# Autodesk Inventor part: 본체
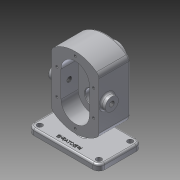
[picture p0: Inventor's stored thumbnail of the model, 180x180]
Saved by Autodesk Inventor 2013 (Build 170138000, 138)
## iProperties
Created: 2019-03
Part Number: 본체
Material: 알루미늄 6061
Document SubType Name: Modeling
Designer: Administrator
Density: 2.71 g/cm^3
Mass: 1193.14 g
Surface Area: 720.724 cm^2
Volume: 440.275 cm^3
Author: Administrator
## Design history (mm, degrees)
sketch "스케치2"
  geometry: L1 (-40, 60)-(40, 60); L2 (40, 60)-(40, -60); L3 (40, -60)-(-40, -60); L4 (-40, -60)-(-40, 60); A1 r 60 centre (0, 0) between (-40, -44.721) and (40, -44.721); A2 r 60 centre (0, 0) between (40, 44.721) and (-40, 44.721); 3 further points
  constraints: 8 end point, 5 point on circle, 4 point on line, 2 centre point, 2 midpoint, 2 parallel, 1 coincident, 1 horizontal, 1 horizontal alignment, 1 perpendicular, 1 vertical alignment
  dimensions: "d0" = 80 distance between parallel lines of L2 L4; "d2" = 120 distance of L3.end L1.start; "d5" = 60 radius of A2; "d6" = 60 radius of A1
extrude "돌출1" new body sketch "스케치2" distance "d7" = 53; taper "d8" = 0 deg
sketch "스케치3"
  geometry: L1 (-40, 44.721)-(-40, -44.721) reference; L2 (-24, 22)-(-24, -22); L3 (24, -22)-(24, 22); A1 r 60 centre (0, 0) between (40, 44.721) and (-40, 44.721) reference; A2 r 24 centre (0, 22) between (24, 22) and (-24, 22); A3 r 24 centre (0, -22) between (-24, -22) and (24, -22)
  constraints: 4 end point, 4 point on circle, 2 centre point, 2 parallel, 2 tangent, 2 vertical alignment
  dimensions: "d9" = 24 radius of A2; "d10" = 24 radius of A3; "d11" = 44 distance of A3.centre A2.centre; "d12" = 22 distance of A1.centre A2.centre
extrude "돌출2" cut sketch "스케치3" distance "d13" = 29; taper "d14" = 0 deg
sketch "스케치4"
  geometry: C1 r 12.5 at (0, 22); C2 r 12.5 at (0, -22); A1 r 24 centre (0, -22) between (-24, -22) and (24, -22) reference; A2 r 24 centre (0, 22) between (24, 22) and (-24, 22) reference; 1 further point
  constraints: 2 centre point, 2 coincident
  dimensions: "d15" = 12.5 radius of C1; "d16" = 12.5 radius of C2
extrude "돌출3" cut sketch "스케치4" distance "d17" = 15; taper "d18" = 0 deg
sketch "스케치5"
  geometry: C1 r 12.5 at (0, 0) reference; C2 r 8.5 at (0, 0); 1 further point
  constraints: 1 centre point, 1 coincident
  dimensions: "d19" = 8.5 radius of C2
extrude "돌출4" cut sketch "스케치5" stored distance "d20" = 15; taper "d21" = 0 deg
sketch "스케치6"
  geometry: C1 r 8.5 at (0, 22) reference; C2 r 19 at (0, 22)
  constraints: 1 centre point, 1 coincident
  dimensions: "d22" = 19 radius of C2
extrude "돌출5" join sketch "스케치6" distance "d23" = 17; taper "d24" = 0 deg
sketch "스케치7"
  geometry: L1 (3, -17)-(41, -17) reference; L2 (30.5, 9)-(30.5, -17) reference; L3 (13.5, 9)-(13.5, -17) reference; L4 (22, 8.572)-(22, -17); L5 (22, -9.7)-(35.5, -9.7); L6 (36, -10.2)-(36, -16.3); L7 (36, -16.3)-(22, -16.3); L8 (22, -16.3)-(22, -9.7); L9 (36, -16.3)-(36.404, -17); L10 (36, -16.3)-(39.088, -16.3); L11 (36, -16.3)-(36, -19.794); A1 r 0.5 centre (35.5, -10.2) between (36, -10.2) and (35.5, -9.7); 2 further points
  constraints: 16 end point, 4 point on line, 3 parallel, 2 horizontal, 2 perpendicular, 2 point on circle, 2 tangent, 1 centre point, 1 midpoint
  dimensions: "d25" = 6.6 distance of point (36, -9.7) L6.end; "d28" = 7.3 distance from line of L4.end L5; "d30" = 28 diameter of L6 L4; "d31" = 30 deg angle of L11 L9; "d32" = 0.5 radius of A1
revolve "회전1" sketch "스케치7" stored, may be unused: angle "d33" = 90 deg
sketch "스케치8"
  geometry: C1 r 12.5 at (0, 22) reference; A1 r 24 centre (0, -22) between (-24, -22) and (24, -22) reference; A2 r 24 centre (0, 22) between (24, 22) and (-24, 22) reference; A3 r 31 centre (0, 22) between (0, 53) and (-31, 22); A4 r 31 centre (0, -22) between (31, -22) and (0, -53); 2 further points
  constraints: 6 point on circle, 4 vertical alignment, 2 centre point, 2 coincident, 2 horizontal alignment
  dimensions: "d34" = 31 radius of A3; "d35" = 31 radius of A4
hole "구멍1" sketch "스케치8" at (0, 53), (-31, 22), (31, 22), (31, -22), (0, -53), (-31, -22) diameter "d36" = 4.134; stored, may be unused: countersink angle "d40" = 90 deg, drill point angle "d42" = 118 deg; dims "d37" = 10, "d38" = 4, "d39" = 2, "d41" = 12
sketch "스케치9"
  geometry: L1 (0, 0)-(0, 89.443) reference; L2 (-53, 0)-(-53, 89.443) reference; C1 r 11 at (-39, 44.721); 2 further points
  constraints: 1 centre point, 1 horizontal alignment, 1 midpoint
  dimensions: "d43" = 22 diameter of C1; "d45" = 14 distance from line of L2 C1.centre
extrude "돌출6" join sketch "스케치9" distance "d46" = 8; taper "d47" = 0 deg
sketch "스케치10"
  geometry: C1 r 11 at (0, 0) reference; 1 further point
sketch "스케치11"
  geometry: C1 r 11 at (0, 0) reference; 1 further point
hole "구멍2" sketch "스케치11" at (0, 0) diameter "d48" = 8.376; stored, may be unused: countersink angle "d52" = 90 deg, drill point angle "d54" = 118 deg; dims "d49" = 30, "d50" = 4, "d51" = 2, "d53" = 12
hole "구멍3" sketch "스케치10" diameter "d55" = 8.376; stored, may be unused: countersink angle "d59" = 90 deg, drill point angle "d61" = 118 deg; dims "d56" = 100, "d57" = 4, "d58" = 2, "d60" = 12
node "작업 평면2"
sketch "스케치12"
  geometry: L1 (40, 53)-(-40, 53) reference; L2 (40, 0)-(-40, 0) reference; L3 (-40, 50)-(-48, 50) reference; L4 (-40, 28)-(-48, 28) reference; L5 (-40, 28)-(-48, 28) reference; L6 (-40, 28)-(-48, 28) reference; L7 (-44, 28)-(-44, 50); L8 (-60, 0)-(60, 0); L9 (60, 0)-(60, 73); L10 (60, 73)-(-60, 73); L11 (-60, 73)-(-60, 0); 3 further points
  constraints: 10 end point, 4 midpoint, 2 coincident, 2 parallel, 1 horizontal, 1 perpendicular
  dimensions: "d63" = 120 distance between parallel lines of L9 L11; "d65" = 73 distance of L10.end L8.start
extrude "돌출7" join sketch "스케치12" distance "d66" = 10; taper "d67" = 0 deg
sketch "스케치13"
  geometry: L1 (60, 0)-(-60, 0) reference; L2 (-60, 0)-(-60, -73) reference; L3 (-60, -73)-(60, -73) reference; L4 (-6, -43)-(6, -43); L5 (6, -43)-(6, 0); L6 (6, 0)-(-6, 0); L7 (-6, 0)-(-6, -43); 4 further points
  constraints: 8 end point, 2 coincident, 2 midpoint, 2 parallel, 1 horizontal, 1 perpendicular, 1 other
  dimensions: "d68" = 12 distance of L6.end L5.end; "d69" = 43 distance of L5.end L4.end; "d70" = 10 distance from line of L3 point (0, -63); "d71" = 60 distance from line of L2 point (0, -63)
feature "엠보싱1" dims "d0" = 80, "d2" = 120, "d5" = 60, "d6" = 60, "d13" = 29, "d72" = 0.5, "d73" = 0
extrude "돌출8" join sketch "스케치13" stored distance "d74" = 10; taper "d75" = 0 deg
fillet "모깎기1" dims "d76" = 10
sketch "스케치14"
  geometry: A1 r 10 centre (-50, -63) between (-60, -63) and (-50, -73) reference; A2 r 10 centre (50, -63) between (50, -73) and (60, -63) reference; A3 r 10 centre (50, -10) between (60, -10) and (50, 0) reference; A4 r 10 centre (-50, -10) between (-50, 0) and (-60, -10) reference; 1 further point
hole "구멍4" sketch "스케치14" at (-50, -63), (-50, -10), (50, -63), (50, -10) diameter "d77" = 9; stored, may be unused: countersink angle "d81" = 90 deg, drill point angle "d83" = 118 deg; dims "d78" = 10, "d79" = 4, "d80" = 2, "d82" = 12
chamfer "모따기1" distance "d84" = 1; stored, may be unused: second distance "d85" = 2, angle "d86" = 45 deg
fillet "모깎기2" dims "d87" = 3
fillet "모깎기3" dims "d88" = 3, "d90" = 10
fillet "모깎기4" dims "d89" = 3
fillet "모깎기5" dims "d91" = 3
fillet "모깎기6" dims "d92" = 3
node "솔리드1"
mirror "대칭1"
node "작업 평면1"
other parameters: "d62" = -78
